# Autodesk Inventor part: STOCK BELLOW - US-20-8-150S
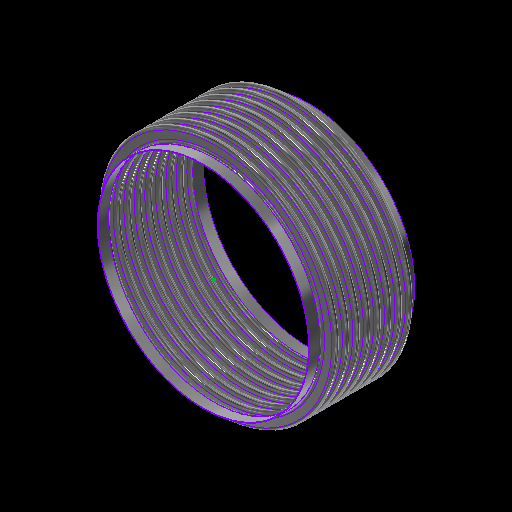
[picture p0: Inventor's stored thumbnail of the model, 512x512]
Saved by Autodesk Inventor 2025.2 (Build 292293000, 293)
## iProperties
Category: 16 GA (0.060 THICK)
RuleStatus: InUse
Created: 2024-01
Part Number: STOCK BELLOW - US-20-8-150S
Project: =STOCK BELLOWS: <Stock Number><SFILL>
Material: ASTM A240-304
Description: =STOCK BELLOWS: <Stock Number>, <SID_> I.D., <SOD_> O.D., <SPLY_> PLY, <Category>, <SNET_CONS> CONS.<PITCH_><STANGENT_> TANGENT<SFILL>
Document SubType Name: Sheet Metal
Designer: GS
Stock Number: U.S-20-8-150S
Surface Area: 22107.3 cm^2
Volume: 1673.42 cm^3
Sheet Metal Rule: Default
Appearance: STAINLESS STEEL
Mass: 13483.2 g
Density: 8.05729 g/cm^3
THK: 0.036
ID: 3.500
OD: 4.250
CONS_: 2
PITCH: 0.500
TANGENT: 0.500
BELLOWS_UPSET: 0.000
d79: 1.000
d82: 1.000
d83: 26.000
d84: 24.000
d174: 8
d214: 8
STHK_: 0.060
SID_: 20.000
SOD_: 22.500
SPITCH_: 1.000
STANGENT__: 1.000
SBELLOWS_UPSET_: 0.000
SDIFF_TAN: 1.000
d252: 2
d275: 2
d287: 0.050
d289: 0.500
d290: 0.000
SOD_NECK: 20 1/8
PLY: 1
PSET: 4.178
PBAR: 1.035
COUNTER: 1.500
NET_TUBE: 3.071
CONS: 2
S_CONS: 0
NET_CONS: 2
ID_M: 88.90 mm
OD_M: 107.95 mm
THK_M: 0.91 mm
ID_U: 3.500 in
OD_U: 4.250 in
THK_U: 0.036 in
TANGENT2: 0.500
TAN_TO_TAN: 1.000 in
d80: 2.571
d81: 10
SID: 2.375
SCONS_: 8
SPITCH: 0.250
STANGENT_: 1.000
SBELLOWS_UPSET: 0.000
SNET_CONS: 8
SS_CONS: 0
SCONS: 8
d190: 8
d191: 1
d192: 1
d193: 8
d194: 0
SIZE: 20.00
PRESSURE: 150
d230: 8
STANGENT: 4.000
SPLY_: 1
d233: 8
d234: 0
d263: 2
d265: 1
d268: 2
d269: 0
d286: 2
d288: 1
d291: 2
d292: 0
SREROLL: 0.750
BLETP: 0.000 ul
PRES_Copy: 85
MATTABLE: 20 GA (0.036 THICK)
PART_NUMBER: U.S-20-8-150S
PITCH_: =, <SPITCH_> PITCH,
CFILL: .
SFILL: .
MESH: ,
COMP: 1.49
EXT: 0.75
LAT: 0.18
ANG: 458
ASR: 5632
LSR: 53644
ANSR: 4993
PRES: 150
COMPM: 14.9
EXTM: 7.45
LATM: 1.80
ASRM: 986.332
PRESM: 10.342
LSRM: 9394.674
ANSRM: 874.424
TEMPMIN: 20
TEMPMAX: 800
TEMPMINM: -7
TEMPMAXM: 427
WEIGHTM: 13.483
WEIGHT: 29.725
Author: GS
Keywords: 20 GA (0.036 THICK)
Comments: =STOCK BELLOW - <STOCK NUMBER>
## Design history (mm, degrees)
sketch "Sketch2"
  geometry: L1 (0, -177.245)-(0, 562.856) reference; L2 (45.364, 0)-(44.45, 0); L3 (48.082, -2.718)-(50.343, -2.718); L4 (48.082, -3.632)-(50.343, -3.632); L5 (50.343, -9.982)-(48.082, -9.982); L6 (50.343, -9.068)-(48.082, -9.068); L7 (45.364, -12.7)-(44.45, -12.7); L8 (48.082, 0)-(48.082, -12.7); L9 (50.343, -6.35)-(53.975, -6.35); L10 (44.45, 0)-(44.45, -12.7); L11 (20.376, 102.841)-(20.376, 101.926); L12 (58.262, 457.127)-(58.262, 349.177); L13 (58.262, 444.427)-(58.262, 336.477); L14 (93.133, -58.817)-(93.133, -71.517); L15 (118.746, -66.401)-(118.746, -66.401); L16 (50.343, -9.068)-(50.343, -9.982); L17 (48.082, -9.068)-(48.082, -9.982); L18 (48.082, -9.525)-(50.343, -9.525); L19 (53.975, 0)-(53.975, -12.7); L20 (-50.343, -9.068)-(-50.343, -9.982); L21 (-50.343, -2.718)-(-48.082, -2.718); L22 (-50.343, -3.632)-(-48.082, -3.632); L23 (-48.082, -9.068)-(-50.343, -9.068); L24 (-50.343, -9.525)-(-48.082, -9.525); L25 (-48.082, -9.982)-(-50.343, -9.982); L26 (-48.082, -9.068)-(-48.082, -9.982); L27 (-44.45, 0.653)-(-44.45, -12.047); L28 (-48.082, -6.35)-(-44.45, -6.35); L29 (-50.343, 0.653)-(-50.343, -12.7); L30 (-53.061, 0)-(-53.975, 0); L31 (-53.975, 0)-(-53.975, -12.7); L32 (-53.061, -12.7)-(-53.975, -12.7); A1 r 2.718 centre (48.082, 0) between (45.364, 0) and (48.082, -2.718); A2 r 3.632 centre (48.082, 0) between (44.45, 0) and (48.082, -3.632); A3 r 3.632 centre (50.343, -6.35) between (50.343, -9.982) and (50.343, -2.718); A4 r 2.718 centre (50.343, -6.35) between (50.343, -9.068) and (50.343, -3.632); A5 r 2.718 centre (48.082, -12.7) between (48.082, -9.982) and (45.364, -12.7); A6 r 3.632 centre (48.082, -12.7) between (48.082, -9.068) and (44.45, -12.7); A7 r 3.175 centre (50.343, -6.35) between (50.343, -9.525) and (53.518, -6.35); A8 r 3.175 centre (48.082, -12.7) between (48.082, -9.525) and (44.907, -12.7); A9 r 2.718 centre (-50.343, -12.7) between (-50.343, -9.982) and (-53.061, -12.7); A10 r 2.718 centre (-48.082, -6.35) between (-48.082, -9.068) and (-48.082, -3.632); A11 r 3.175 centre (-48.082, -6.35) between (-48.082, -9.525) and (-44.907, -6.35); A12 r 3.632 centre (-48.082, -6.35) between (-48.082, -9.982) and (-48.082, -2.718); A13 r 3.175 centre (-50.343, -12.7) between (-50.343, -9.525) and (-53.518, -12.7); A14 r 3.632 centre (-50.343, -12.7) between (-50.343, -9.068) and (-53.975, -12.7); A15 r 2.718 centre (-50.343, 0) between (-53.061, 0) and (-50.343, -2.718); A16 r 3.632 centre (-50.343, 0) between (-53.975, 0) and (-50.343, -3.632); 10 further points
  constraints: 62 end point, 38 point on circle, 20 tangent, 16 centre point, 12 parallel, 9 midpoint, 7 vertical, 6 coincident, 6 concentric, 6 point on line, 4 equal radius, 4 perpendicular, 3 horizontal, 1 collinear, 1 horizontal alignment, 10 other
  dimensions: "THK" = 0.9144 distance of L11.start L11.end; "ID" = 88.9 distance of L11.end point (20.376, 13.026); "OD" = 107.95 distance of L12.start L12.end; "PITCH" = 12.7 distance of L12.start L13.start; "TANGENT" = 12.7 distance of L14.start L14.end; "BELLOWS_UPSET" = 0 distance of L15.start L15.end; "d43" = 88.9 diameter of L10 L1 (= ID); "d44" = 107.95 diameter of L9.end L1 (= OD); "d45" = 0.9144 distance between parallel lines of L5 L6 (computed from THK, PLY); "d46" = 3.6322 radius of A3 (computed from PITCH, THK, PLY); "UPSET_PITCH" = 12.7 distance of L2.end L7.end (derived); "SIDEWALL_ANGLE" = 360 deg dimension on L3 L9 (derived); "CON_GAP" = 5.4356 distance of point (48.082, -9.068) point (48.082, -3.632) (derived); "TAN1" = 4.98728 dimension on A8 (derived); "TAN2" = 4.98728 dimension on A7 (derived); "LEG1" = 2.2606 distance of L18.start L18.end (derived); "d278" = 0.9144 distance between parallel lines of L25 L23 (derived); "d279" = 3.6322 radius of A12 (derived); "d280" = 12.7 distance of L30.end L31.end (derived); "d281" = 360 deg dimension on L21 L28 (derived); "d282" = 5.4356 distance of point (-50.343, -9.068) point (-50.343, -3.632) (derived); "d283" = 4.98728 dimension on A13 (derived); "d284" = 4.98728 dimension on A11 (derived); "d285" = 2.2606 distance of L24.start L24.end (derived); "d293" = 88.9 diameter of L27 L1 (derived); "d294" = 107.95 diameter of L31 L1 (derived)
  node "Sketch Rectangular Pattern1" dims "d31" = 25.4, "ID" = 88.9
  node "Sketch Rectangular Pattern2" dims "d39" = 25.4, "PITCH" = 12.7
revolve "CONS" stored, may be unused: angle "d48" = 90 deg
node "BELLOW MIDPLANE"
pattern_linear "Rectangular Pattern2" dims "d52" = 12.7 (= UPSET_PITCH)
sketch "Sketch5"
  geometry: C1 r 45.364 at (0, 0) reference; C2 r 44.45 at (0, 0) reference
extrude "TANGENT" new body sketch "Sketch5" distance "d53" = 12.7 (= TANGENT); taper "d54" = 0 deg
revolve "SAMETAN" stored, may be unused: angle "d65" = 90 deg
revolve "DIFFTAN" stored, may be unused: angle "d70" = 90 deg
sketch "Sketch9"
  geometry: L1 (53.319, 0)-(-53.319, 0) reference; L2 (0, -17.78)-(0, 17.78) reference; L3 (38.085, 0)-(-38.085, 0); L4 (38.085, -11.906)-(38.085, 11.906); L5 (25.385, -11.906)-(25.385, 11.906); L6 (13.15, 11.906)-(13.15, -11.906); L7 (-25.385, -11.906)-(-25.385, 11.906); L8 (-38.085, -11.906)-(-38.085, 11.906); L9 (37.291, -11.906)-(37.291, 11.906); L10 (38.085, -11.906)-(37.291, -11.906); L11 (38.085, 11.906)-(37.291, 11.906); L12 (13.546, 11.906)-(12.753, 11.906); L13 (12.753, 11.906)-(12.753, -11.906); L14 (12.753, -11.906)-(13.546, -11.906); L15 (13.546, -11.906)-(13.546, 11.906); L16 (-13.546, 11.906)-(-13.546, -11.906); L17 (-13.15, 11.906)-(-13.15, -11.906); L18 (-13.546, -11.906)-(-12.753, -11.906); L19 (-12.753, -11.906)-(-12.753, 11.906); L20 (-12.753, 11.906)-(-13.546, 11.906); L21 (-38.085, -11.906)-(-37.291, -11.906); L22 (-37.291, -11.906)-(-37.291, 11.906); L23 (-37.291, 11.906)-(-38.085, 11.906); L24 (-38.085, 11.906)-(-38.085, -11.906); L25 (38.085, -0.397)-(-38.085, -0.397); L26 (-38.085, -0.397)-(-38.085, 0.397); L27 (-38.085, 0.397)-(38.085, 0.397); L28 (38.085, 0.397)-(38.085, -0.397); L29 (-38.085, 11.906)-(38.085, 11.906); L30 (38.085, 11.906)-(38.085, 12.7); L31 (38.085, 12.7)-(-38.085, 12.7); L32 (-38.085, 12.7)-(-38.085, 11.906); L33 (38.085, -11.906)-(-38.085, -11.906); L34 (-38.085, -11.906)-(-38.085, -12.7); L35 (-38.085, -12.7)-(38.085, -12.7); L36 (38.085, -12.7)-(38.085, -11.906); 30 further points
  constraints: 68 end point, 13 midpoint, 13 parallel, 8 horizontal, 7 perpendicular, 6 equal length, 3 point on line, 2 vertical, 14 other
  dimensions: "d115" = 23.8125 distance of L4.start L4.end (derived); "d116" = 12.7 distance between parallel lines of L4 L5 (derived); "d117" = 12.23516 distance between parallel lines of L5 L6 (derived); "d125" = 38.53427 distance between parallel lines of L7 L6 (derived); "d127" = 12.7 distance between parallel lines of L8 L7 (derived); "d128" = 24.93516 distance between parallel lines of L6 L4 (derived); "d130" = 76.16943 distance between parallel lines of L8 L4 (derived); "RULER_THK" = 0.79375 distance between parallel lines of L4 L9; "d135" = 0.79375 distance of L13.end L14.end (derived); "d138" = 26.29911 distance of L13.end L16.end (derived); "d143" = 0.79375 distance of L22.end L8.end (derived); "d144" = 0.79375 distance between parallel lines of L27 L25 (derived)
extrude "RULER" join sketch "Sketch9" distance "d149" = 0.79375 (derived); taper "d150" = 0 deg
extrude "BARS" join sketch "Sketch9" distance "d151" = 0.79375 (derived); taper "d152" = 0 deg
pattern_linear "Rectangular Pattern4" dims "d155" = 26.29911 (derived)
sketch "Sketch13"
  geometry: L1 (93.149, -52.467)-(93.149, -77.867); L2 (255.524, 0)-(254, 0); L3 (255.524, -25.4)-(254, -25.4); L4 (278.638, -19.812)-(261.112, -19.812); L5 (278.638, -18.288)-(261.112, -18.288); L6 (278.638, -12.7)-(285.75, -12.7); L7 (261.112, -5.588)-(278.638, -5.588); L8 (261.112, 0)-(261.112, -25.4); L9 (254, 0)-(254, -25.4); L10 (58.254, 75.069)-(58.254, -496.431); L11 (58.254, 49.669)-(58.254, -521.831); L12 (58.254, -1.131)-(58.254, -572.631); L13 (58.254, -26.531)-(58.254, -598.031); L14 (58.254, -51.931)-(58.254, -623.431); L15 (58.254, -77.331)-(58.254, -648.831); L16 (58.254, -102.731)-(58.254, -674.231); L17 (58.254, 24.269)-(58.254, -547.231); L18 (20.376, 103.45)-(20.376, 101.926); L19 (261.112, -7.112)-(278.638, -7.112); L20 (0, -829.767)-(0, 258.986) reference; L21 (-57.15, 0)-(342.9, 0) reference; A1 r 5.588 centre (261.112, 0) between (255.524, 0) and (261.112, -5.588); A2 r 5.588 centre (261.112, -25.4) between (261.112, -19.812) and (255.524, -25.4); A3 r 7.112 centre (261.112, -25.4) between (261.112, -18.288) and (254, -25.4); A4 r 5.588 centre (278.638, -12.7) between (278.638, -18.288) and (278.638, -7.112); A5 r 7.112 centre (278.638, -12.7) between (278.638, -19.812) and (278.638, -5.588); A6 r 7.112 centre (261.112, 0) between (254, 0) and (261.112, -7.112); 6 further points; 1 other entity
  constraints: 38 end point, 15 point on circle, 9 tangent, 6 centre point, 6 parallel, 5 vertical alignment, 4 point on line, 4 vertical, 3 coincident, 3 concentric, 2 collinear, 2 equal radius, 1 horizontal, 1 perpendicular, 23 other
  dimensions: "SBELLOWS_UPSET_" = 0 distance of point (118.762, -66.401) point (118.762, -66.401); "STOTAL_THK_BELLOW__" = 1.524 distance between parallel lines of L4 L5 (derived); "d224" = 7.112 radius of A5 (derived); "d225" = 25.4 distance of L2.end L3.end (derived); "SSIDEWALL_ANGLE_" = 360 deg dimension on L7 L6 (derived); "SSCON_GAP_" = 11.176 distance of point (261.112, -18.288) point (261.112, -7.112) (derived); "d235" = 508 diameter of L9 L20 (derived); "d236" = 571.5 diameter of L6.end L20 (derived)
  node "Sketch Rectangular Pattern4" dims "d228" = 25.4
  node "Sketch Rectangular Pattern5" dims "d229" = 25.4
revolve "SBELLOW" stored, may be unused: angle "d197" = 90 deg
pattern_linear "Rectangular Pattern5" dims "d204" = 25.4 (derived)
revolve "STANGENT" stored, may be unused: angle "d240" = 90 deg
revolve "SSAMETAN" stored, may be unused: angle "d241" = 90 deg
revolve "SDIFFTAN" stored, may be unused: angle "d246" = 90 deg
revolve "INVCON" stored, may be unused: angle "d295" = 90 deg
pattern_linear "Rectangular Pattern6" dims "d298" = 12.7 (derived)
revolve "INVTANGENT" stored, may be unused: angle "d302" = 90 deg
revolve "INVSAMETAN" stored, may be unused: angle "d307" = 90 deg
revolve "INVDIFFTAN" stored, may be unused: angle "d312" = 90 deg
sketch "ID BELLOW MOUNT CALC"
  geometry: L1 (44.45, 0)-(38.1, 0); L2 (38.1, 0)-(38.1, 12.7); L3 (38.1, 12.7)-(44.45, 12.7); L4 (44.45, 12.7)-(44.45, 0); L5 (36.513, 12.7)-(35.598, 12.7); L6 (35.598, 12.7)-(35.598, 0); L7 (35.598, 0)-(36.513, 0); L8 (36.513, 0)-(36.513, 12.7); L9 (0, -2.54)-(0, 15.24) reference; L10 (-8.89, 0)-(53.34, 0) reference; 1 further point
  constraints: 16 end point, 5 parallel, 2 collinear, 2 horizontal, 2 perpendicular
  dimensions: "d314" = 12.7 distance of L5.end L6.end (derived); "d315" = 0.9144 distance of L5.start L5.end (derived); "IG" = 1.5875 distance between parallel lines of L2 L8; "PIPE_OD" = 88.9 diameter of L4 L9; "PIPE_WALL" = 6.35 distance of L2.end L3.end; "ID_MT_BELLOW" = 71.1962 diameter of L6 L9 (derived)
revolve "CFILL" stored, may be unused: angle "d320" = 90 deg
pattern_linear "Rectangular Pattern7" dims "d323" = 12.7 (derived)
revolve "SFILL" stored, may be unused: angle "d324" = 90 deg
pattern_linear "Rectangular Pattern8" dims "d327" = 25.4 (derived)
node "STOCK BELLOW MIDPLANE"
node "BELLOW"
sketch "Sketch6"
  geometry: L1 (-12.7, 45.364)-(0, 45.364); L2 (0, 45.364)-(0, 44.45); L3 (0, 44.45)-(-12.7, 44.45); L4 (-12.7, 44.45)-(-12.7, 45.364); L5 (10.16, 0)-(-60.96, 0) reference; L6 (-38.1, -89.422)-(-38.1, 153.44) reference; 1 further point
  constraints: 8 end point, 2 parallel, 1 horizontal, 1 perpendicular
  dimensions: "d61" = 12.7 distance of L2.end L3.end (derived); "d62" = 0.9144 distance of L1.end L2.end (derived); "d63" = 88.9 diameter of L3 L5 (derived); "d64" = 25.4 distance between parallel lines of L4 L6 (derived)
sketch "Sketch12"
  geometry: 1 further point
sketch "Sketch14"
  geometry: L1 (-25.4, 255.524)-(0, 255.524); L2 (0, 255.524)-(0, 254); L3 (0, 254)-(-25.4, 254); L4 (-25.4, 254)-(-25.4, 255.524); L5 (5.08, 0)-(-30.48, 0) reference; L6 (0, -51.105)-(0, 306.629) reference; 1 further point
  constraints: 8 end point, 2 parallel, 1 collinear, 1 horizontal, 1 perpendicular
  dimensions: "d237" = 1.524 distance of L3.end L1.start (derived); "d238" = 508 diameter of L3 L5 (derived); "d239" = 25.4 distance of L1.start L1.end (derived); "SOD_NECK" = 511.048 diameter of L1 L5 (derived)
sketch "Sketch15"
  geometry: L1 (-51.105, 0)-(306.629, 0) reference; L2 (254, -203.2)-(255.524, -203.2); L3 (255.524, -203.2)-(255.524, -228.6); L4 (255.524, -228.6)-(254, -228.6); L5 (254, -228.6)-(254, -203.2); L6 (0, -276.86)-(0, 60.96) reference; 1 further point
  constraints: 8 end point, 2 parallel, 1 horizontal, 1 perpendicular
  dimensions: "d205" = 25.4 distance of L4.end L2.start (derived); "d206" = 1.524 distance of L3.end L4.end (derived); "d207" = 508 diameter of L5 L6 (derived); "d208" = 203.2 distance between parallel lines of L1 L2 (derived)
node "TANGENT_"
node "SAME_TAN"
sketch "Sketch8"
  geometry: L1 (45.364, -25.4)-(44.45, -25.4); L2 (44.45, -25.4)-(44.45, -38.1); L3 (44.45, -38.1)-(45.364, -38.1); L4 (45.364, -38.1)-(45.364, -25.4); L5 (0, -48.26)-(0, 22.86) reference; L6 (-89.422, 0)-(153.44, 0) reference; 1 further point
  constraints: 8 end point, 2 parallel, 1 horizontal, 1 perpendicular
  dimensions: "d66" = 88.9 diameter of L2 L5 (derived); "TOTAL_THK_BELLOW" = 0.9144 distance of L2.end L3.end (derived); "d68" = 25.4 distance between parallel lines of L1 L6 (derived); "d69" = 12.7 distance of L1.end L2.end (derived)
node "DIFF_TAN"
node "Sketch Rectangular Pattern3" dims "d138" = 26.29911 (derived), "d141" = 25.4
node "SBELLOW_"
node "STANGENT_"
node "SSAME_TAN"
sketch "Sketch16"
  geometry: L1 (255.524, -203.2)-(254, -203.2); L2 (254, -203.2)-(254, -228.6); L3 (254, -228.6)-(255.524, -228.6); L4 (255.524, -228.6)-(255.524, -203.2); L5 (0, -276.86)-(0, 60.96) reference; L6 (-51.105, 0)-(306.629, 0) reference; 1 further point
  constraints: 8 end point, 2 parallel, 1 horizontal, 1 perpendicular
  dimensions: "SDIFF_TAN" = 25.4 distance of L3.end L1.start; "d243" = 1.524 distance of L2.end L3.end (derived); "d244" = 203.2 distance between parallel lines of L1 L6 (derived); "d245" = 508 diameter of L2 L5 (derived)
node "SDIFF_TAN"
body "Solid15"
sketch "Sketch17"
  geometry: L1 (53.975, 12.7)-(53.061, 12.7); L2 (53.061, 12.7)-(53.061, 0); L3 (53.061, 0)-(53.975, 0); L4 (53.975, 0)-(53.975, 12.7); L5 (0, -2.54)-(0, 15.24) reference; L6 (-10.795, 0)-(64.77, 0) reference; 2 further points
  constraints: 8 end point, 2 parallel, 1 horizontal, 1 midpoint, 1 perpendicular, 1 point on line
  dimensions: "INVTANGENT" = 12.7 distance of L3.end L1.start (derived); "d300" = 0.9144 distance of L1.start L1.end (derived); "d301" = 107.95 diameter of L4 L5 (derived)
body "Solid16"
sketch "Sketch18"
  geometry: L1 (53.975, -25.4)-(53.061, -25.4); L2 (53.061, -25.4)-(53.061, -38.1); L3 (53.061, -38.1)-(53.975, -38.1); L4 (53.975, -38.1)-(53.975, -25.4); L5 (-10.795, 0)-(64.77, 0) reference; L6 (0, -48.26)-(0, 22.86) reference; 1 further point
  constraints: 8 end point, 2 parallel, 1 horizontal, 1 perpendicular
  dimensions: "d303" = 25.4 distance between parallel lines of L1 L5 (derived); "d304" = 12.7 distance of L3.end L1.start (derived); "d305" = 0.9144 distance of L2.end L3.end (derived); "d306" = 107.95 diameter of L4 L6 (derived)
body "Solid17"
sketch "Sketch19"
  geometry: L1 (53.975, -25.4)-(53.061, -25.4); L2 (53.061, -25.4)-(53.061, -38.1); L3 (53.061, -38.1)-(53.975, -38.1); L4 (53.975, -38.1)-(53.975, -25.4); L5 (0, -48.26)-(0, 22.86) reference; L6 (-10.795, 0)-(64.77, 0) reference; 1 further point
  constraints: 8 end point, 2 parallel, 1 horizontal, 1 perpendicular
  dimensions: "d308" = 12.7 distance of L1.end L2.end (derived); "d309" = 107.95 diameter of L4 L5 (derived); "d310" = 0.9144 distance of L2.end L3.end (derived); "d311" = 25.4 distance between parallel lines of L1 L6 (derived)
body "Solid18"
body "Solid19"
body "Solid20"
other parameters: "BMPL" = -101.6, "PSET" = 106.1212 (computed from OD, THK, PLY) [user parameter], "PBAR" = 26.29911 (= 0.570796 x PITCH + OD - ID) [user parameter; used in 1 equation term], "COUNTER" = 15 [user parameter], "NET_TUBE" = 77.99823 (computed from CONS_, PBAR, TANGENT) [user parameter], "S_CONS" = 0 [user parameter; used in 1 equation term], "ID_M" = 88.9 (= ID) [user parameter], "OD_M" = 107.95 (= OD) [user parameter], "THK_M" = 0.9144 (= THK) [user parameter], "ID_U" = 88.9 (= ID) [user parameter], "OD_U" = 107.95 (= OD) [user parameter], "THK_U" = 0.9144 (= THK) [user parameter], "D_UNITS" = 0 [user parameter], "TANGENT2" = 12.7 [user parameter], "TAN_TO_TAN" = 25.4 [user parameter], "OD_NECK" = 90.7288 [user parameter], "d79" = 25.4, "d80" = 65.29823 [user parameter], "d82" = 25.4, "d83" = 660.4, "d84" = 609.6, "sa_0" = 4, "FRAME_THK" = 0.79375 [user parameter], "CON_FLAT" = 12.23516 [user parameter], "SID" = 60.325 [user parameter], "SPITCH" = 6.35 [user parameter], "STANGENT_" = 25.4 [user parameter], "SBELLOWS_UPSET" = 0 [user parameter], "SS_CONS" = 0 [user parameter], "STAN_TO_TAN_" = 203.2 [user parameter], "d100" = 1.524 [user parameter], "d191" = 25.4 [user parameter], "d194" = 0 [user parameter], "STANGENT" = 101.6 [user parameter], "d234" = 0 [user parameter], "SUPSET_PITCH_" = 25.4 [user parameter], "d269" = 0 [user parameter], "d287" = 1.27, "d289" = 12.7, "d290" = 0, "d292" = 0 [user parameter], "Thickness" = 3.048 (derived), "KFactor" = 4.4, "BendRadius" = 3.048 (derived), "BendReliefWidth" = 3.048 (derived), "BendReliefDepth" = 1.524 (derived), "CornerReliefSize" = 12.192 (derived), "SeamGap" = 0.00508, "MinimumRemnant" = 6.096 (derived), "TransitionRadius" = 3.048 (derived), "JacobiRadiusSize" = 3.048 (derived), "GapSize" = 3.048 (derived), "SREROLL" = 19.05 [user parameter], "CUR_STK_PITCH" = 25.4 [user parameter], "d328" = -101.6 (derived), "ASR" = 56320 [user parameter], "LSR" = 536440 [user parameter], "ANSR" = 49930 [user parameter], "BLETP" = 0 [user parameter], "ASRM" = 9863.3216 [user parameter], "PRESM" = 103.41975 [user parameter], "LSRM" = 93946.7372 [user parameter], "ANSRM" = 8744.2409 [user parameter], "TEMPMIN" = 2664.83333 [user parameter], "TEMPMAX" = 6998.16667 [user parameter], "TEMPMINM" = 2664.83333 [user parameter], "TEMPMAXM" = 6998.16667 [user parameter], "WEIGHT" = 134.83242 [user parameter], "WEIGHTM" = 0.13483 [user parameter]
